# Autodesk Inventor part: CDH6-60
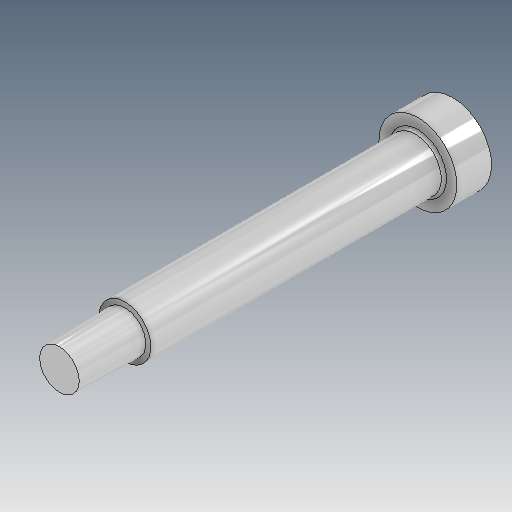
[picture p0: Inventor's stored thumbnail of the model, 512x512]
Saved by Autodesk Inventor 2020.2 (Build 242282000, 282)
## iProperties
Created: 2020-04
Part Number: CDH6-60
Material: Ogólny
Description: Kołek stemplowy prosty
Document SubType Name: Modeling
Designer: F.Stasiak
Density: 1 g/cm^3
Appearance: Domyślna
Catalog Web Link: www.expertbooks.pl
Manager: www.cadconsulting.pl
Company: Fabian Stasiak CAD Consulting
Author: F.Stasiak
Subject: Zbiór ćwiczeń. Autodesk Inventor 2020. Kurs Professional
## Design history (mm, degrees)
node "Forma_ZEGAR_2610_ZEGAR_260_Rdzeń formujący1_Base"
feature "Solid1::Forma_ZEGAR_2610_ZEGAR_260_Rdzeń formujący1_Base"
tag "Bryła wyprowadzona1"
node "Bryła1"
feature "Forma_ZEGAR_2610_ZEGAR_260_Rdzeń formujący1_Base_Bodies"
